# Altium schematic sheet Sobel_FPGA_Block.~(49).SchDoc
size A1
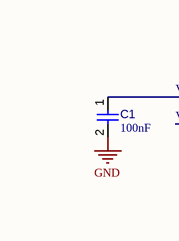
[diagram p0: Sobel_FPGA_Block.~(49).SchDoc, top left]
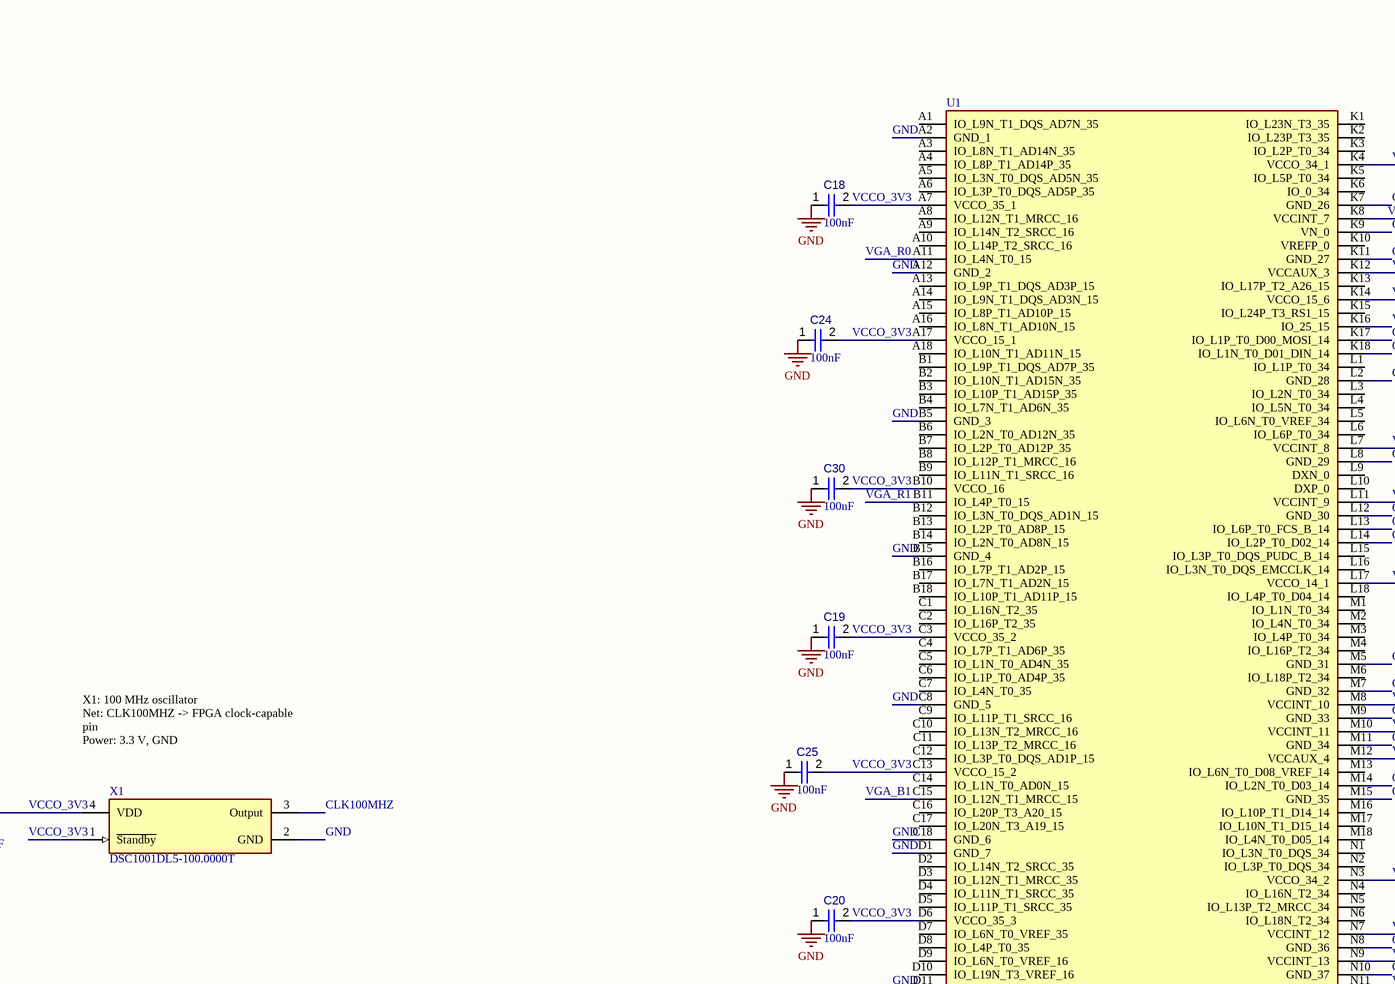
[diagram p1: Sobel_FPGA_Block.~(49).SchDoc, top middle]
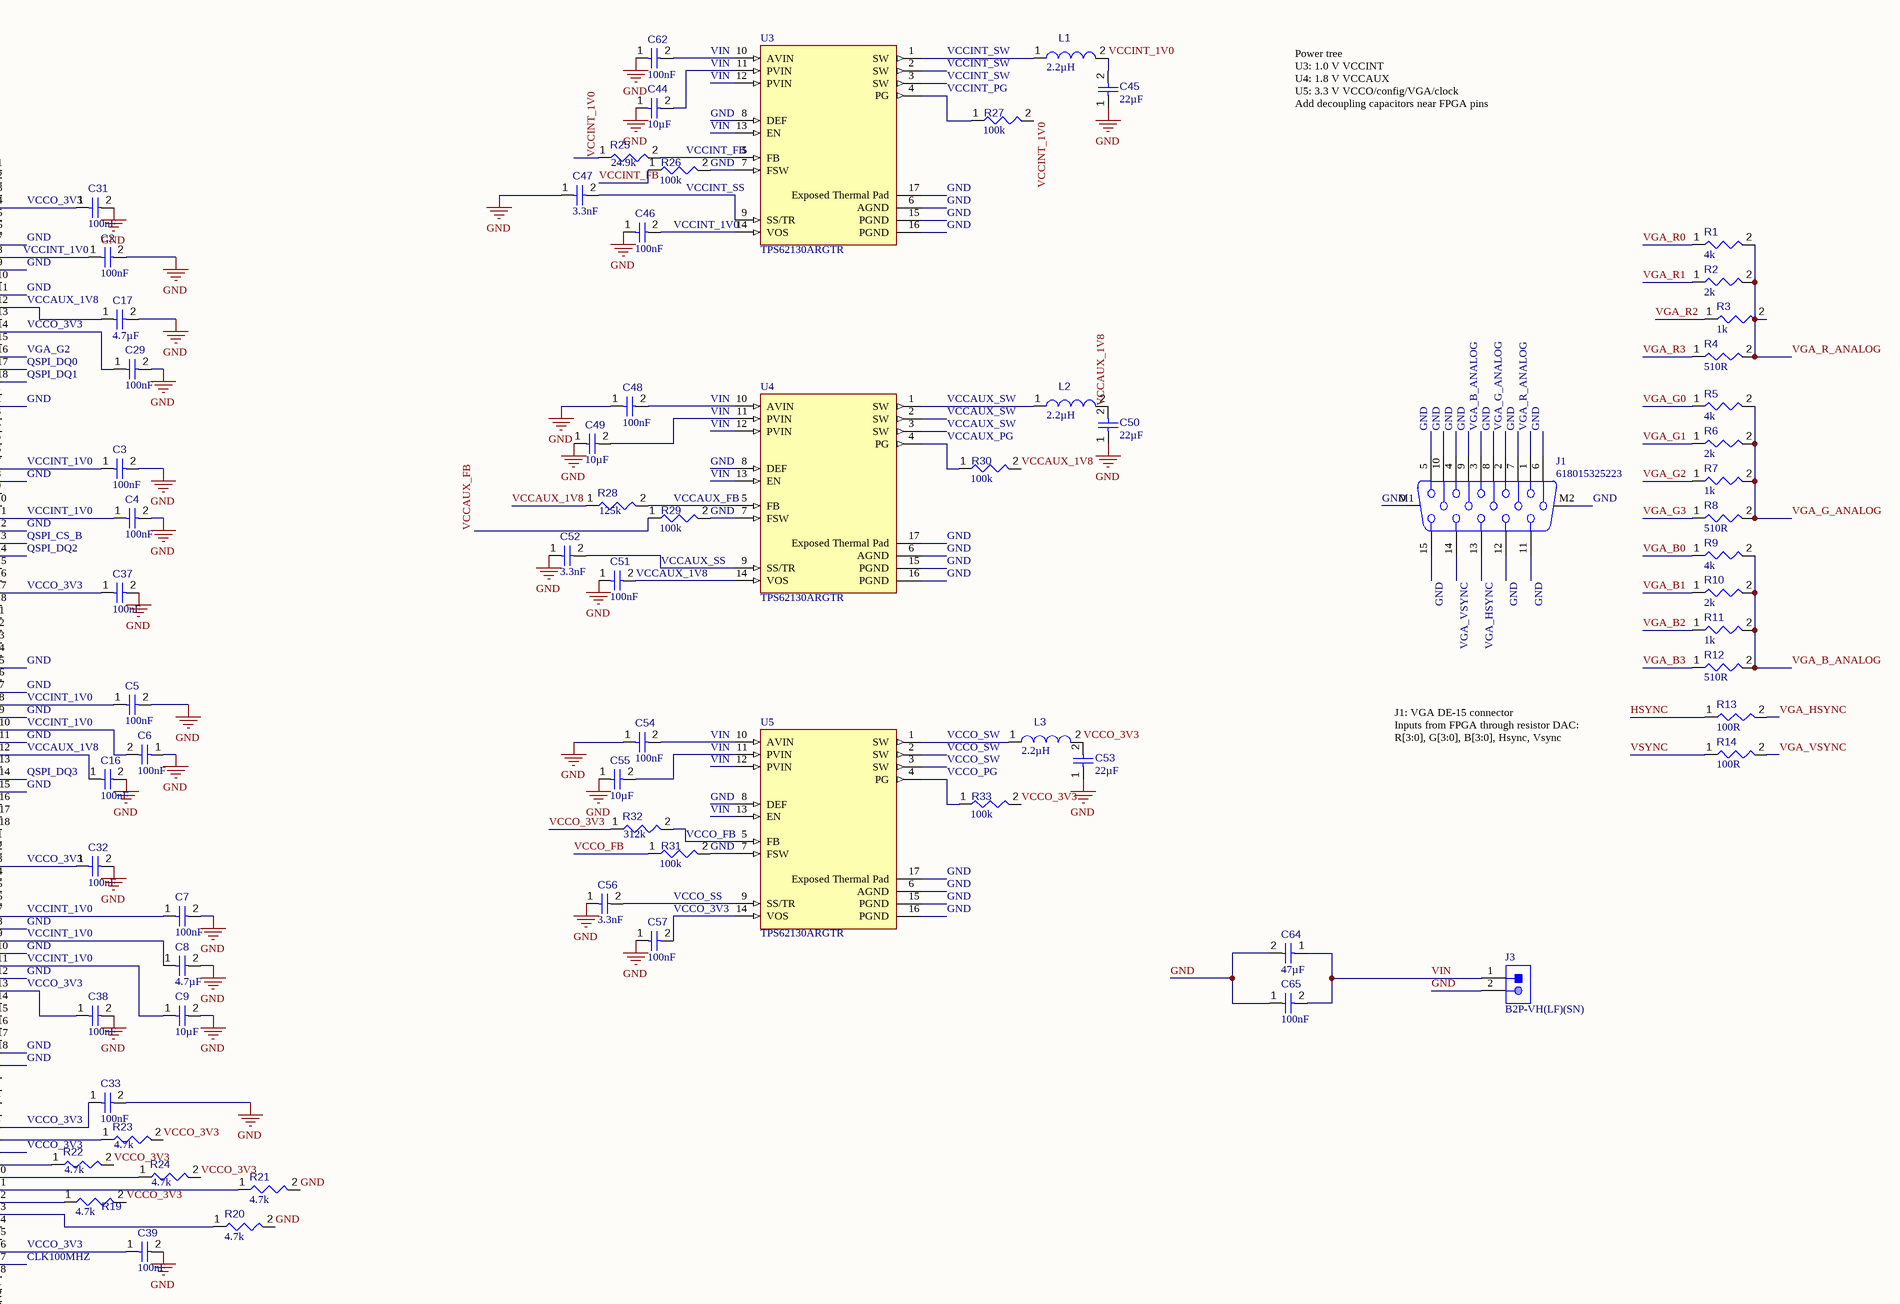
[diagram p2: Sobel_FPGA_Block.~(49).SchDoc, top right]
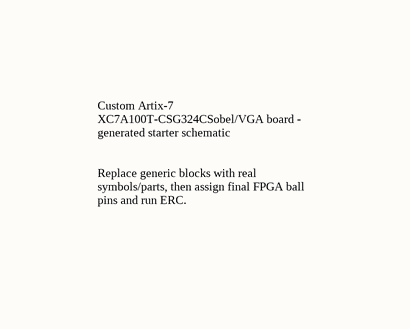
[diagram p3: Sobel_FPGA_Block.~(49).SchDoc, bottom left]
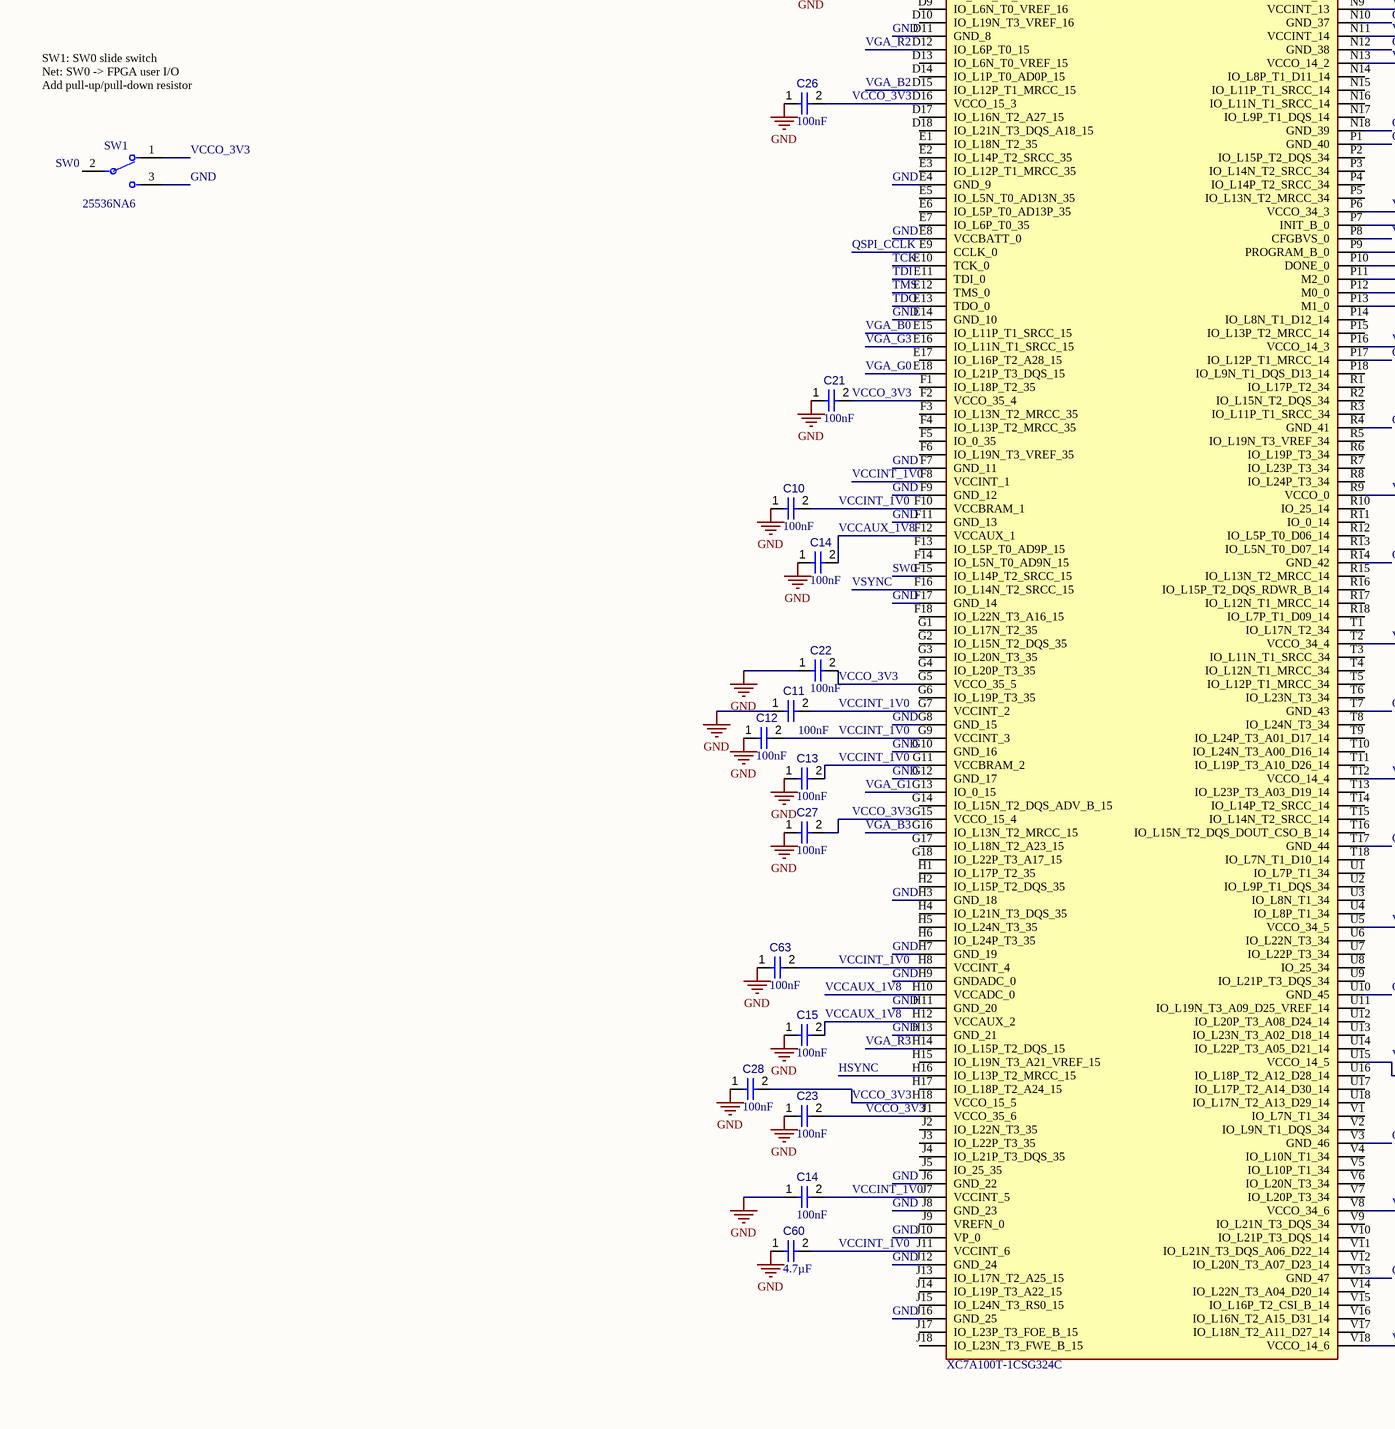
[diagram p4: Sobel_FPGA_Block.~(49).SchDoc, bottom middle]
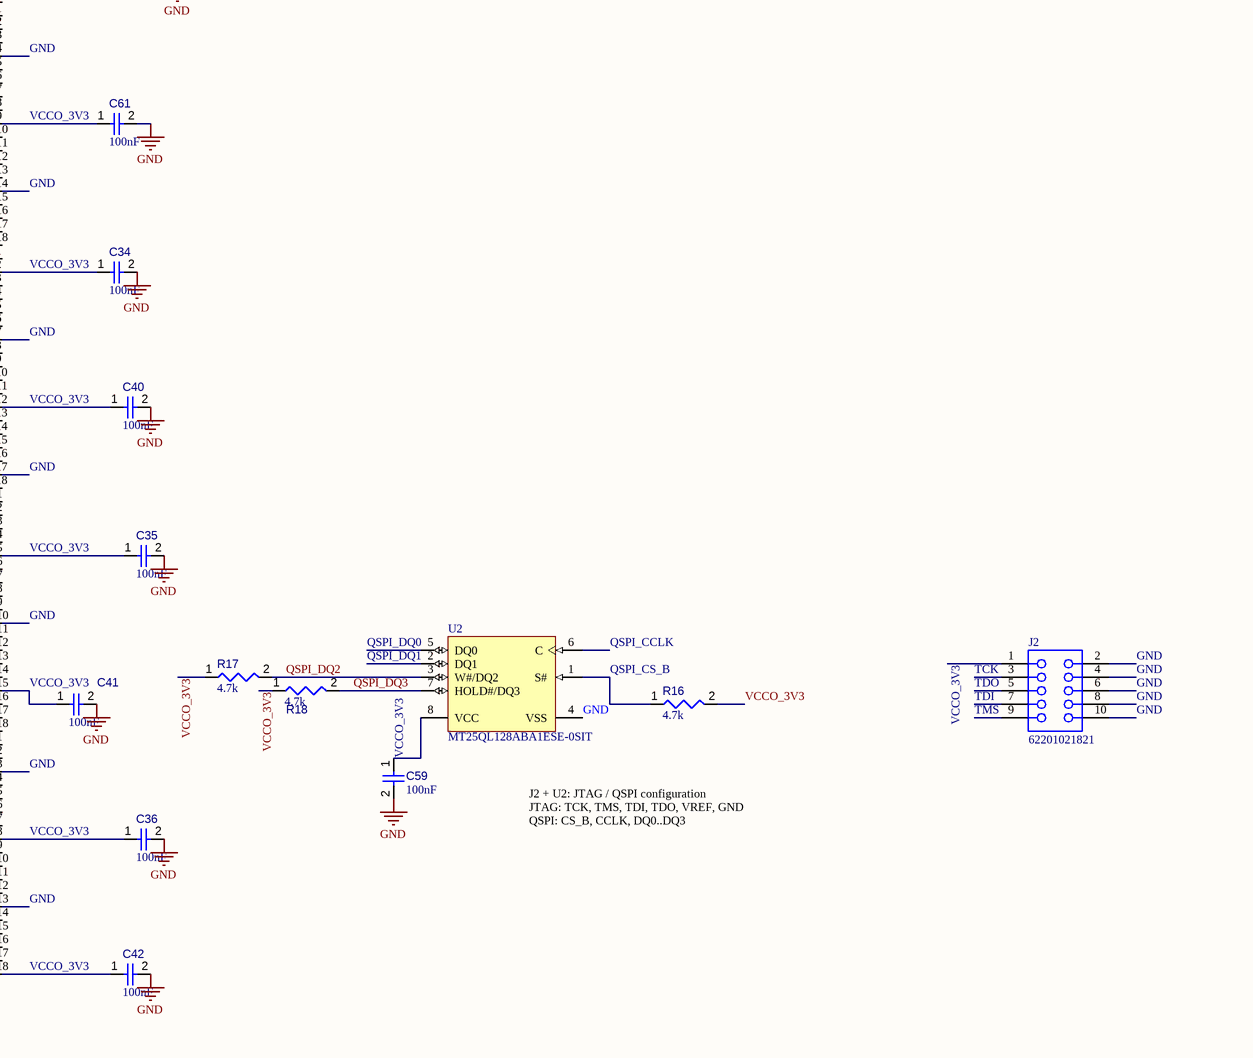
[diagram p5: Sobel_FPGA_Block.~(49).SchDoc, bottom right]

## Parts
(Parts that share a designator on the sheet are numbered #1, #2 ... from top to bottom, then left to right.)
C1  value 100nF  [CAPC1005X56X25NL10T15]  (hidden comment: Capacitor 6.8 nF +/- 10% 16 V 0402)
C2  value 100nF  [CAPC1005X56X25NL10T15]  (hidden comment: Capacitor 6.8 nF +/- 10% 16 V 0402)
C3  value 100nF  [CAPC1005X56X25NL10T15]  (hidden comment: Capacitor 6.8 nF +/- 10% 16 V 0402)
C4  value 100nF  [CAPC1005X56X25NL10T15]  (hidden comment: Capacitor 6.8 nF +/- 10% 16 V 0402)
C5  value 100nF  [CAPC1005X56X25NL10T15]  (hidden comment: Capacitor 6.8 nF +/- 10% 16 V 0402)
C6  value 100nF  [CAPC1005X56X25NL10T15]  (hidden comment: Capacitor 6.8 nF +/- 10% 16 V 0402)
C7  value 100nF  [CAPC1005X56X25NL10T15]  (hidden comment: Capacitor 6.8 nF +/- 10% 16 V 0402)
C8  value 4.7µF  [CAPC3216X180X50NL20T25]  (hidden comment: Capacitor 10 uF +/- 10% 16 V 1206)
C9  value 10µF  [CAPC3216X180X50NL20T25]  (hidden comment: Capacitor 10 uF +/- 10% 16 V 1206)
C10  value 100nF  [CAPC1005X56X25NL10T15]  (hidden comment: Capacitor 6.8 nF +/- 10% 16 V 0402)
C11  value 100nF  [CAPC1005X56X25NL10T15]  (hidden comment: Capacitor 6.8 nF +/- 10% 16 V 0402)
C12  value 100nF  [CAPC1005X56X25NL10T15]  (hidden comment: Capacitor 6.8 nF +/- 10% 16 V 0402)
C13  value 100nF  [CAPC1005X56X25NL10T15]  (hidden comment: Capacitor 6.8 nF +/- 10% 16 V 0402)
C14#1  value 100nF  [CAPC1005X56X25NL10T15]  (hidden comment: Capacitor 6.8 nF +/- 10% 16 V 0402)
C14#2  value 100nF  [CAPC1005X56X25NL10T15]  (hidden comment: Capacitor 6.8 nF +/- 10% 16 V 0402)
C15  value 100nF  [CAPC1005X56X25NL10T15]  (hidden comment: Capacitor 6.8 nF +/- 10% 16 V 0402)
C16  value 100nF  [CAPC1005X56X25NL10T15]  (hidden comment: Capacitor 6.8 nF +/- 10% 16 V 0402)
C17  value 4.7µF  [CAPC3216X180X50NL20T25]  (hidden comment: Capacitor 10 uF +/- 10% 16 V 1206)
C18  value 100nF  [CAPC1005X56X25NL10T15]  (hidden comment: Capacitor 6.8 nF +/- 10% 16 V 0402)
C19  value 100nF  [CAPC1005X56X25NL10T15]  (hidden comment: Capacitor 6.8 nF +/- 10% 16 V 0402)
C20  value 100nF  [CAPC1005X56X25NL10T15]  (hidden comment: Capacitor 6.8 nF +/- 10% 16 V 0402)
C21  value 100nF  [CAPC1005X56X25NL10T15]  (hidden comment: Capacitor 6.8 nF +/- 10% 16 V 0402)
C22  value 100nF  [CAPC1005X56X25NL10T15]  (hidden comment: Capacitor 6.8 nF +/- 10% 16 V 0402)
C23  value 100nF  [CAPC1005X56X25NL10T15]  (hidden comment: Capacitor 6.8 nF +/- 10% 16 V 0402)
C24  value 100nF  [CAPC1005X56X25NL10T15]  (hidden comment: Capacitor 6.8 nF +/- 10% 16 V 0402)
C25  value 100nF  [CAPC1005X56X25NL10T15]  (hidden comment: Capacitor 6.8 nF +/- 10% 16 V 0402)
C26  value 100nF  [CAPC1005X56X25NL10T15]  (hidden comment: Capacitor 6.8 nF +/- 10% 16 V 0402)
C27  value 100nF  [CAPC1005X56X25NL10T15]  (hidden comment: Capacitor 6.8 nF +/- 10% 16 V 0402)
C28  value 100nF  [CAPC1005X56X25NL10T15]  (hidden comment: Capacitor 6.8 nF +/- 10% 16 V 0402)
C29  value 100nF  [CAPC1005X56X25NL10T15]  (hidden comment: Capacitor 6.8 nF +/- 10% 16 V 0402)
C30  value 100nF  [CAPC1005X56X25NL10T15]  (hidden comment: Capacitor 6.8 nF +/- 10% 16 V 0402)
C31  value 100nF  [CAPC1005X56X25NL10T15]  (hidden comment: Capacitor 6.8 nF +/- 10% 16 V 0402)
C32  value 100nF  [CAPC1005X56X25NL10T15]  (hidden comment: Capacitor 6.8 nF +/- 10% 16 V 0402)
C33  value 100nF  [CAPC1005X56X25NL10T15]  (hidden comment: Capacitor 6.8 nF +/- 10% 16 V 0402)
C34  value 100nF  [CAPC1005X56X25NL10T15]  (hidden comment: Capacitor 6.8 nF +/- 10% 16 V 0402)
C35  value 100nF  [CAPC1005X56X25NL10T15]  (hidden comment: Capacitor 6.8 nF +/- 10% 16 V 0402)
C36  value 100nF  [CAPC1005X56X25NL10T15]  (hidden comment: Capacitor 6.8 nF +/- 10% 16 V 0402)
C37  value 100nF  [CAPC1005X56X25NL10T15]  (hidden comment: Capacitor 6.8 nF +/- 10% 16 V 0402)
C38  value 100nF  [CAPC1005X56X25NL10T15]  (hidden comment: Capacitor 6.8 nF +/- 10% 16 V 0402)
C39  value 100nF  [CAPC1005X56X25NL10T15]  (hidden comment: Capacitor 6.8 nF +/- 10% 16 V 0402)
C40  value 100nF  [CAPC1005X56X25NL10T15]  (hidden comment: Capacitor 6.8 nF +/- 10% 16 V 0402)
C41  value 100nF  [CAPC1005X56X25NL10T15]  (hidden comment: Capacitor 6.8 nF +/- 10% 16 V 0402)
C42  value 100nF  [CAPC1005X56X25NL10T15]  (hidden comment: Capacitor 6.8 nF +/- 10% 16 V 0402)
C44  value 10µF  [CAPC3216X180X50NL20T25]  (hidden comment: Capacitor 10 uF +/- 10% 16 V 1206)
C45  value 22µF  [CAPC3216X180X50NL20T25]  (hidden comment: Capacitor 10 uF +/- 10% 16 V 1206)
C46  value 100nF  [CAPC1005X56X25NL10T15]  (hidden comment: Capacitor 6.8 nF +/- 10% 16 V 0402)
C47  value 3.3nF  [CAPC1005X56X25NL10T15]  (hidden comment: Capacitor 6.8 nF +/- 10% 16 V 0402)
C48  value 100nF  [CAPC1005X56X25NL10T15]  (hidden comment: Capacitor 6.8 nF +/- 10% 16 V 0402)
C49  value 10µF  [CAPC3216X180X50NL20T25]  (hidden comment: Capacitor 10 uF +/- 10% 16 V 1206)
C50  value 22µF  [CAPC3216X180X50NL20T25]  (hidden comment: Capacitor 10 uF +/- 10% 16 V 1206)
C51  value 100nF  [CAPC1005X56X25NL10T15]  (hidden comment: Capacitor 6.8 nF +/- 10% 16 V 0402)
C52  value 3.3nF  [CAPC1005X56X25NL10T15]  (hidden comment: Capacitor 6.8 nF +/- 10% 16 V 0402)
C53  value 22µF  [CAPC3216X180X50NL20T25]  (hidden comment: Capacitor 10 uF +/- 10% 16 V 1206)
C54  value 100nF  [CAPC1005X56X25NL10T15]  (hidden comment: Capacitor 6.8 nF +/- 10% 16 V 0402)
C55  value 10µF  [CAPC3216X180X50NL20T25]  (hidden comment: Capacitor 10 uF +/- 10% 16 V 1206)
C56  value 3.3nF  [CAPC1005X56X25NL10T15]  (hidden comment: Capacitor 6.8 nF +/- 10% 16 V 0402)
C57  value 100nF  [CAPC1005X56X25NL10T15]  (hidden comment: Capacitor 6.8 nF +/- 10% 16 V 0402)
C59  value 100nF  [CAPC1005X56X25NL10T15]  (hidden comment: Capacitor 6.8 nF +/- 10% 16 V 0402)
C60  value 4.7µF  [CAPC3216X180X50NL20T25]  (hidden comment: Capacitor 10 uF +/- 10% 16 V 1206)
C61  value 100nF  [CAPC1005X56X25NL10T15]  (hidden comment: Capacitor 6.8 nF +/- 10% 16 V 0402)
C62  value 100nF  [CAPC1005X56X25NL10T15]  (hidden comment: Capacitor 6.8 nF +/- 10% 16 V 0402)
C63  value 100nF  [CAPC1005X56X25NL10T15]  (hidden comment: Capacitor 6.8 nF +/- 10% 16 V 0402)
C64  value 47µF  [CAPC3216X180X50NL20T25]  (hidden comment: Capacitor 10 uF +/- 10% 16 V 1206)
C65  value 100nF  [CAPC1005X56X25NL10T15]  (hidden comment: Capacitor 6.8 nF +/- 10% 16 V 0402)
J1  618015325223  [618015325223]
J2  62201021821  [62201021821]
J3  B2P-VH(LF)(SN)  [JST-B2P-VH(LF)(SN)_V]
L1  value 2.2µH  [SUSUMU-PCMB063T_V]  (hidden comment: PCMB063T-2R2MS)
L2  value 2.2µH  [SUSUMU-PCMB063T_V]  (hidden comment: PCMB063T-2R2MS)
L3  value 2.2µH  [SUSUMU-PCMB063T_V]  (hidden comment: PCMB063T-2R2MS)
R1  value 4k  [RESA60-630X240]  (hidden comment: MFR-25FBF52-475R)
R2  value 2k  [RESA60-630X240]  (hidden comment: MFR-25FBF52-475R)
R3  value 1k  [RESA60-630X240]  (hidden comment: MFR-25FBF52-475R)
R4  value 510R  [RESA60-630X240]  (hidden comment: MFR-25FBF52-475R)
R5  value 4k  [RESA60-630X240]  (hidden comment: MFR-25FBF52-475R)
R6  value 2k  [RESA60-630X240]  (hidden comment: MFR-25FBF52-475R)
R7  value 1k  [RESA60-630X240]  (hidden comment: MFR-25FBF52-475R)
R8  value 510R  [RESA60-630X240]  (hidden comment: MFR-25FBF52-475R)
R9  value 4k  [RESA60-630X240]  (hidden comment: MFR-25FBF52-475R)
R10  value 2k  [RESA60-630X240]  (hidden comment: MFR-25FBF52-475R)
R11  value 1k  [RESA60-630X240]  (hidden comment: MFR-25FBF52-475R)
R12  value 510R  [RESA60-630X240]  (hidden comment: MFR-25FBF52-475R)
R13  value 100R  [RESA60-630X240]  (hidden comment: MFR-25FBF52-475R)
R14  value 100R  [RESA60-630X240]  (hidden comment: MFR-25FBF52-475R)
R16  value 4.7k  [RESC0402(1005)_L]  (hidden comment: 84D5KR2F)
R17  value 4.7k  [RESC0402(1005)_L]  (hidden comment: 84D5KR2F)
R18  value 4.7k  [RESC0402(1005)_L]  (hidden comment: 84D5KR2F)
R19  value 4.7k  [RESC0402(1005)_L]  (hidden comment: 84D5KR2F)
R20  value 4.7k  [RESC0402(1005)_L]  (hidden comment: 84D5KR2F)
R21  value 4.7k  [RESC0402(1005)_L]  (hidden comment: 84D5KR2F)
R22  value 4.7k  [RESC0402(1005)_L]  (hidden comment: 84D5KR2F)
R23  value 4.7k  [RESC0402(1005)_L]  (hidden comment: 84D5KR2F)
R24  value 4.7k  [RESC0402(1005)_L]  (hidden comment: 84D5KR2F)
R25  value 24.9k  [RESC0402(1005)_L]  (hidden comment: 84D5KR2F)
R26  value 100k  [RESC0402(1005)_L]  (hidden comment: 84D5KR2F)
R27  value 100k  [RESC0402(1005)_L]  (hidden comment: 84D5KR2F)
R28  value 125k  [RESC0402(1005)_L]  (hidden comment: 84D5KR2F)
R29  value 100k  [RESC0402(1005)_L]  (hidden comment: 84D5KR2F)
R30  value 100k  [RESC0402(1005)_L]  (hidden comment: 84D5KR2F)
R31  value 100k  [RESC0402(1005)_L]  (hidden comment: 84D5KR2F)
R32  value 312k  [RESC0402(1005)_L]  (hidden comment: 84D5KR2F)
R33  value 100k  [RESC0402(1005)_L]  (hidden comment: 84D5KR2F)
SW1  25536NA6  [FP-25536NA6-0]
U1  XC7A100T-1CSG324C  [BGA324C80P18X18_1500X1500X150]
U2  MT25QL128ABA1ESE-0SIT  [MICT-SE-8_M]
U3  TPS62130ARGTR  [FP-RGT0016C-IPC_C]
U4  TPS62130ARGTR  [FP-RGT0016C-IPC_C]
U5  TPS62130ARGTR  [FP-RGT0016C-IPC_C]
X1  DSC1001DL5-100.0000T  [FP-CDFN2520-4LD-PL-1-MFG]

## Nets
GND: C1.2 C2.2 C3.2 C4.2 C5.2 C6.1 C7.2 C8.2 C9.2 C10.1 C11.1 C12.1 C13.1 C14#1.1 C14#2.1 C15.1 C16.2 C17.2 C18.1 C19.1 C20.1 C21.1 C22.1 C23.1 C24.1 C25.1 C26.1 C27.1 C28.1 C29.2 C30.1 C31.2 C32.2 C33.2 C34.2 C35.2 C36.2 C37.2 C38.2 C39.2 C40.2 C41.2 C42.2 C44.1 C45.1 C46.1 C47.1 C48.1 C49.1 C50.1 C51.1 C52.1 C53.1 C54.1 C55.1 C56.1 C57.1 C59.2 C60.1 C61.2 C62.1 C63.1 C64.2 C65.1 J1.4 J1.5 J1.6 J1.7 J1.8 J1.9 J1.10 J1.11 J1.12 J1.15 J1.M1 J1.M2 J2.2 J2.4 J2.6 J2.8 J2.10 J3.2 R20.2 R21.2 R26.2 R29.2 R31.2 SW1.3 U1.A2(GND_1) U1.A12(GND_2) U1.B5(GND_3) U1.B15(GND_4) U1.C8(GND_5) U1.C18(GND_6) U1.D1(GND_7) U1.D11(GND_8) U1.E4(GND_9) U1.E8(VCCBATT_0) U1.E14(GND_10) U1.F7(GND_11) U1.F9(GND_12) U1.F11(GND_13) U1.F17(GND_14) U1.G8(GND_15) U1.G10(GND_16) U1.G12(GND_17) U1.H3(GND_18) U1.H7(GND_19) U1.H9(GNDADC_0) U1.H11(GND_20) U1.H13(GND_21) U1.J6(GND_22) U1.J8(GND_23) U1.J10(VP_0) U1.J12(GND_24) U1.J16(GND_25) U1.K7(GND_26) U1.K9(VN_0) U1.K11(GND_27) U1.L2(GND_28) U1.L8(GND_29) U1.L12(GND_30) U1.M5(GND_31) U1.M7(GND_32) U1.M9(GND_33) U1.M11(GND_34) U1.M15(GND_35) U1.N8(GND_36) U1.N10(GND_37) U1.N12(GND_38) U1.N18(GND_39) U1.P1(GND_40) U1.R4(GND_41) U1.R14(GND_42) U1.T7(GND_43) U1.T17(GND_44) U1.U10(GND_45) U1.V3(GND_46) U1.V13(GND_47) U2.4(VSS) U3.6(AGND) U3.7(FSW) U3.8(DEF) U3.15(PGND) U3.16(PGND) U3.17(Exposed_Thermal_Pad) U4.6(AGND) U4.7(FSW) U4.8(DEF) U4.15(PGND) U4.16(PGND) U4.17(Exposed_Thermal_Pad) U5.6(AGND) U5.7(FSW) U5.8(DEF) U5.15(PGND) U5.16(PGND) U5.17(Exposed_Thermal_Pad) X1.2(GND)
 VCCO_3V3: C1.1 C18.2 C19.2 C20.2 C21.2 C22.2 C23.2 C24.2 C25.2 C26.2 C27.2 C28.2 C29.1 C30.2 C31.1 C32.1 C33.1 C34.1 C35.1 C36.1 C37.1 C38.1 C39.1 C40.1 C41.1 C42.1 C53.2 C57.2 C59.1 C61.1 J2.1 L3.2 R16.2 R17.1 R18.1 R19.2 R22.2 R23.2 R24.2 R32.1 R33.2 SW1.1 U1.A7(VCCO_35_1) U1.A17(VCCO_15_1) U1.B10(VCCO_16) U1.C3(VCCO_35_2) U1.C13(VCCO_15_2) U1.D6(VCCO_35_3) U1.D16(VCCO_15_3) U1.F2(VCCO_35_4) U1.G5(VCCO_35_5) U1.G15(VCCO_15_4) U1.H18(VCCO_15_5) U1.J1(VCCO_35_6) U1.K4(VCCO_34_1) U1.K14(VCCO_15_6) U1.L17(VCCO_14_1) U1.N3(VCCO_34_2) U1.N13(VCCO_14_2) U1.P6(VCCO_34_3) U1.P8(CFGBVS_0) U1.P16(VCCO_14_3) U1.R9(VCCO_0) U1.T2(VCCO_34_4) U1.T12(VCCO_14_4) U1.U5(VCCO_34_5) U1.U15(VCCO_14_5) U1.V8(VCCO_34_6) U1.V18(VCCO_14_6) U2.8(VCC) U5.14(VOS) X1.1(~{Standby}) X1.4(VDD)  [also labelled VCCO_3V3]
CLK100MHZ: U1.P17(IO_L12P_T1_MRCC_14) X1.3(Output)
HSYNC: R13.1 U1.H16(IO_L13P_T2_MRCC_15)
QSPI_CCLK: U1.E9(CCLK_0) U2.6(C)
QSPI_CS_B: R16.1 U1.L13(IO_L6P_T0_FCS_B_14) U2.1(S#)
QSPI_DQ0: U1.K17(IO_L1P_T0_D00_MOSI_14) U2.5(DQ0)
QSPI_DQ1: U1.K18(IO_L1N_T0_D01_DIN_14) U2.2(DQ1)
QSPI_DQ2: R17.2 U1.L14(IO_L2P_T0_D02_14) U2.3(W#/DQ2)
QSPI_DQ3: R18.2 U1.M14(IO_L2N_T0_D03_14) U2.7(HOLD#/DQ3)
SW0: U1.F15(IO_L14P_T2_SRCC_15)
TCK: J2.3 U1.E10(TCK_0)
TDI: J2.7 U1.E11(TDI_0)
TDO: J2.5 U1.E13(TDO_0)
TMS: J2.9 U1.E12(TMS_0)
VCCAUX_1V8: C14#1.2 C15.2 C16.1 C17.1 C50.2 C51.2 L2.2 R28.1 R30.2 U1.F12(VCCAUX_1) U1.H10(VCCADC_0) U1.H12(VCCAUX_2) U1.K12(VCCAUX_3) U1.M12(VCCAUX_4) U4.14(VOS)
VCCAUX_FB: R28.2 R29.1 U4.5(FB)  [also labelled VCCAUX_FB ]
VCCAUX_PG: R30.1 U4.4(PG)
VCCAUX_SS: C52.2 U4.9(SS/TR)
VCCAUX_SW: L2.1 U4.1(SW) U4.2(SW) U4.3(SW)
VCCINT_1V0: C2.1 C3.1 C4.1 C5.1 C6.2 C7.1 C8.1 C9.1 C10.2 C11.2 C12.2 C13.2 C14#2.2 C45.2 C46.2 C60.2 C63.2 L1.2 R25.1 R27.2 U1.F8(VCCINT_1) U1.F10(VCCBRAM_1) U1.G7(VCCINT_2) U1.G9(VCCINT_3) U1.G11(VCCBRAM_2) U1.H8(VCCINT_4) U1.J7(VCCINT_5) U1.J11(VCCINT_6) U1.K8(VCCINT_7) U1.L7(VCCINT_8) U1.L11(VCCINT_9) U1.M8(VCCINT_10) U1.M10(VCCINT_11) U1.N7(VCCINT_12) U1.N9(VCCINT_13) U1.N11(VCCINT_14) U3.14(VOS)
VCCINT_FB: R25.2 R26.1 U3.5(FB)
VCCINT_PG: R27.1 U3.4(PG)
VCCINT_SS: C47.2 U3.9(SS/TR)
VCCINT_SW: L1.1 U3.1(SW) U3.2(SW) U3.3(SW)
VCCO_FB: R31.1 R32.2 U5.5(FB)
VCCO_PG: R33.1 U5.4(PG)
VCCO_SS: C56.2 U5.9(SS/TR)
VCCO_SW: L3.1 U5.1(SW) U5.2(SW) U5.3(SW)
VGA_B0: R9.1 U1.E15(IO_L11P_T1_SRCC_15)
VGA_B1: R10.1 U1.C15(IO_L12N_T1_MRCC_15)
VGA_B2: R11.1 U1.D15(IO_L12P_T1_MRCC_15)
VGA_B3: R12.1 U1.G16(IO_L13N_T2_MRCC_15)
VGA_B_ANALOG: J1.3 R9.2 R10.2 R11.2 R12.2
VGA_G0: R5.1 U1.E18(IO_L21P_T3_DQS_15)
VGA_G1: R6.1 U1.G13(IO_0_15)
VGA_G2: R7.1 U1.K16(IO_25_15)
VGA_G3: R8.1 U1.E16(IO_L11N_T1_SRCC_15)
VGA_G_ANALOG: J1.2 R5.2 R6.2 R7.2 R8.2
VGA_HSYNC: J1.13 R13.2
VGA_R0: R1.1 U1.A11(IO_L4N_T0_15)
VGA_R1: R2.1 U1.B11(IO_L4P_T0_15)
VGA_R2: R3.1 U1.D12(IO_L6P_T0_15)
VGA_R3: R4.1 U1.H14(IO_L15P_T2_DQS_15)
VGA_R_ANALOG: J1.1 R1.2 R2.2 R3.2 R4.2
VGA_VSYNC: J1.14 R14.2
VIN: C44.2 C48.2 C49.2 C54.2 C55.2 C62.2 C64.1 C65.2 J3.1 U3.10(AVIN) U3.11(PVIN) U3.12(PVIN) U3.13(EN) U4.10(AVIN) U4.11(PVIN) U4.12(PVIN) U4.13(EN) U5.10(AVIN) U5.11(PVIN) U5.12(PVIN) U5.13(EN)
VSYNC: R14.1 U1.F16(IO_L14N_T2_SRCC_15)
NetR19_1: R19.1 U1.P12(M0_0)
NetR20_1: R20.1 U1.P13(M1_0)
NetR21_1: R21.1 U1.P11(M2_0)
NetR22_1: R22.1 U1.P9(PROGRAM_B_0)
NetR23_1: R23.1 U1.P7(INIT_B_0)
NetR24_1: R24.1 U1.P10(DONE_0)

Not connected (* = marked no-connect by the designer): SW1 2; U1 A1(IO_L9N_T1_DQS_AD7N_35) A3(IO_L8N_T1_AD14N_35) A4(IO_L8P_T1_AD14P_35) A5(IO_L3N_T0_DQS_AD5N_35) A6(IO_L3P_T0_DQS_AD5P_35) A8(IO_L12N_T1_MRCC_16) A9(IO_L14N_T2_SRCC_16) A10(IO_L14P_T2_SRCC_16) A13(IO_L9P_T1_DQS_AD3P_15) A14(IO_L9N_T1_DQS_AD3N_15) A15(IO_L8P_T1_AD10P_15) A16(IO_L8N_T1_AD10N_15) A18(IO_L10N_T1_AD11N_15) B1(IO_L9P_T1_DQS_AD7P_35) B2(IO_L10N_T1_AD15N_35) B3(IO_L10P_T1_AD15P_35) B4(IO_L7N_T1_AD6N_35) B6(IO_L2N_T0_AD12N_35) B7(IO_L2P_T0_AD12P_35) B8(IO_L12P_T1_MRCC_16) B9(IO_L11N_T1_SRCC_16) B12(IO_L3N_T0_DQS_AD1N_15) B13(IO_L2P_T0_AD8P_15) B14(IO_L2N_T0_AD8N_15) B16(IO_L7P_T1_AD2P_15) B17(IO_L7N_T1_AD2N_15) B18(IO_L10P_T1_AD11P_15) C1(IO_L16N_T2_35) C2(IO_L16P_T2_35) C4(IO_L7P_T1_AD6P_35) C5(IO_L1N_T0_AD4N_35) C6(IO_L1P_T0_AD4P_35) C7(IO_L4N_T0_35) C9(IO_L11P_T1_SRCC_16) C10(IO_L13N_T2_MRCC_16) C11(IO_L13P_T2_MRCC_16) C12(IO_L3P_T0_DQS_AD1P_15) C14(IO_L1N_T0_AD0N_15) C16(IO_L20P_T3_A20_15) C17(IO_L20N_T3_A19_15) D2(IO_L14N_T2_SRCC_35) D3(IO_L12N_T1_MRCC_35) D4(IO_L11N_T1_SRCC_35) D5(IO_L11P_T1_SRCC_35) D7(IO_L6N_T0_VREF_35) D8(IO_L4P_T0_35) D9(IO_L6N_T0_VREF_16) D10(IO_L19N_T3_VREF_16) D13(IO_L6N_T0_VREF_15) D14(IO_L1P_T0_AD0P_15) D17(IO_L16N_T2_A27_15) D18(IO_L21N_T3_DQS_A18_15) E1(IO_L18N_T2_35) E2(IO_L14P_T2_SRCC_35) E3(IO_L12P_T1_MRCC_35) E5(IO_L5N_T0_AD13N_35) E6(IO_L5P_T0_AD13P_35) E7(IO_L6P_T0_35) E17(IO_L16P_T2_A28_15) F1(IO_L18P_T2_35) F3(IO_L13N_T2_MRCC_35) F4(IO_L13P_T2_MRCC_35) F5(IO_0_35) F6(IO_L19N_T3_VREF_35) F13(IO_L5P_T0_AD9P_15) F14(IO_L5N_T0_AD9N_15) F18(IO_L22N_T3_A16_15) G1(IO_L17N_T2_35) G2(IO_L15N_T2_DQS_35) G3(IO_L20N_T3_35) G4(IO_L20P_T3_35) G6(IO_L19P_T3_35) G14(IO_L15N_T2_DQS_ADV_B_15) G17(IO_L18N_T2_A23_15) G18(IO_L22P_T3_A17_15) H1(IO_L17P_T2_35) H2(IO_L15P_T2_DQS_35) H4(IO_L21N_T3_DQS_35) H5(IO_L24N_T3_35) H6(IO_L24P_T3_35) H15(IO_L19N_T3_A21_VREF_15) H17(IO_L18P_T2_A24_15) J2(IO_L22N_T3_35) J3(IO_L22P_T3_35) J4(IO_L21P_T3_DQS_35) J5(IO_25_35) J9(VREFN_0) J13(IO_L17N_T2_A25_15) J14(IO_L19P_T3_A22_15) J15(IO_L24N_T3_RS0_15) J17(IO_L23P_T3_FOE_B_15) J18(IO_L23N_T3_FWE_B_15) K1(IO_L23N_T3_35) K2(IO_L23P_T3_35) K3(IO_L2P_T0_34) K5(IO_L5P_T0_34) K6(IO_0_34) K10(VREFP_0) K13(IO_L17P_T2_A26_15) K15(IO_L24P_T3_RS1_15) L1(IO_L1P_T0_34) L3(IO_L2N_T0_34) L4(IO_L5N_T0_34) L5(IO_L6N_T0_VREF_34) L6(IO_L6P_T0_34) L9(DXN_0) L10(DXP_0) L15(IO_L3P_T0_DQS_PUDC_B_14) L16(IO_L3N_T0_DQS_EMCCLK_14) L18(IO_L4P_T0_D04_14) M1(IO_L1N_T0_34) M2(IO_L4N_T0_34) M3(IO_L4P_T0_34) M4(IO_L16P_T2_34) M6(IO_L18P_T2_34) M13(IO_L6N_T0_D08_VREF_14) M16(IO_L10P_T1_D14_14) M17(IO_L10N_T1_D15_14) M18(IO_L4N_T0_D05_14) N1(IO_L3N_T0_DQS_34) N2(IO_L3P_T0_DQS_34) N4(IO_L16N_T2_34) N5(IO_L13P_T2_MRCC_34) N6(IO_L18N_T2_34) N14(IO_L8P_T1_D11_14) N15(IO_L11P_T1_SRCC_14) N16(IO_L11N_T1_SRCC_14) N17(IO_L9P_T1_DQS_14) P2(IO_L15P_T2_DQS_34) P3(IO_L14N_T2_SRCC_34) P4(IO_L14P_T2_SRCC_34) P5(IO_L13N_T2_MRCC_34) P14(IO_L8N_T1_D12_14) P15(IO_L13P_T2_MRCC_14) P18(IO_L9N_T1_DQS_D13_14) R1(IO_L17P_T2_34) R2(IO_L15N_T2_DQS_34) R3(IO_L11P_T1_SRCC_34) R5(IO_L19N_T3_VREF_34) R6(IO_L19P_T3_34) R7(IO_L23P_T3_34) R8(IO_L24P_T3_34) R10(IO_25_14) R11(IO_0_14) R12(IO_L5P_T0_D06_14) R13(IO_L5N_T0_D07_14) R15(IO_L13N_T2_MRCC_14) R16(IO_L15P_T2_DQS_RDWR_B_14) R17(IO_L12N_T1_MRCC_14) R18(IO_L7P_T1_D09_14) T1(IO_L17N_T2_34) T3(IO_L11N_T1_SRCC_34) T4(IO_L12N_T1_MRCC_34) T5(IO_L12P_T1_MRCC_34) T6(IO_L23N_T3_34) T8(IO_L24N_T3_34) T9(IO_L24P_T3_A01_D17_14) T10(IO_L24N_T3_A00_D16_14) T11(IO_L19P_T3_A10_D26_14) T13(IO_L23P_T3_A03_D19_14) T14(IO_L14P_T2_SRCC_14) T15(IO_L14N_T2_SRCC_14) T16(IO_L15N_T2_DQS_DOUT_CSO_B_14) T18(IO_L7N_T1_D10_14) U1(IO_L7P_T1_34) U2(IO_L9P_T1_DQS_34) U3(IO_L8N_T1_34) U4(IO_L8P_T1_34) U6(IO_L22N_T3_34) U7(IO_L22P_T3_34) U8(IO_25_34) U9(IO_L21P_T3_DQS_34) U11(IO_L19N_T3_A09_D25_VREF_14) U12(IO_L20P_T3_A08_D24_14) U13(IO_L23N_T3_A02_D18_14) U14(IO_L22P_T3_A05_D21_14) U16(IO_L18P_T2_A12_D28_14) U17(IO_L17P_T2_A14_D30_14) U18(IO_L17N_T2_A13_D29_14) V1(IO_L7N_T1_34) V2(IO_L9N_T1_DQS_34) V4(IO_L10N_T1_34) V5(IO_L10P_T1_34) V6(IO_L20N_T3_34) V7(IO_L20P_T3_34) V9(IO_L21N_T3_DQS_34) V10(IO_L21P_T3_DQS_14) V11(IO_L21N_T3_DQS_A06_D22_14) V12(IO_L20N_T3_A07_D23_14) V14(IO_L22N_T3_A04_D20_14) V15(IO_L16P_T2_CSI_B_14) V16(IO_L16N_T2_A15_D31_14) V17(IO_L18N_T2_A11_D27_14)

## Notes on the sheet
- Power tree
  U3: 1.0 V VCCINT
  U4: 1.8 V VCCAUX
  U5: 3.3 V VCCO/config/VGA/clock
  Add decoupling capacitors near FPGA pins
- X1: 100 MHz oscillator
  Net: CLK100MHZ -> FPGA clock-capable pin
  Power: 3.3 V, GND
- J1: VGA DE-15 connector
  Inputs from FPGA through resistor DAC:
  R[3:0], G[3:0], B[3:0], Hsync, Vsync
- (near SW1) SW1: SW0 slide switch
  Net: SW0 -> FPGA user I/O
  Add pull-up/pull-down resistor
- Custom Artix-7 XC7A100T-CSG324CSobel/VGA board - generated starter schematic
- Replace generic blocks with real symbols/parts, then assign final FPGA ball pins and run ERC.
- J2 + U2: JTAG / QSPI configuration
  JTAG: TCK, TMS, TDI, TDO, VREF, GND
  QSPI: CS_B, CCLK, DQ0..DQ3
- Labels drawn without touching a wire or pin: SW0

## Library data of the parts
C1-C7 C10-C13 C14#1 C14#2 C15 C16 C18-C42 C46-C48 C51 C52 C54 C56 C57 C59 C61-C63 C65 = CMP-001-00000-6: Chip Capacitor, 6.8 nF, +/- 10%, 16 V, 0402 (1005 Metric); Capacitor Type: Ceramic; Voltage Rating: 16V
C8 C9 C17 C44 C45 C49 C50 C53 C55 C60 C64 = CMP-001-00016-6: Chip Capacitor, 10 uF, +/- 10%, 16 V, 1206 (3216 Metric); Capacitor Type: Ceramic; Voltage Rating: 16V
J1 = CMP-002-00072-1: D-sub, Female High Density Angled Pcb Connector Without Hex Screw, 15 Pins
J2 = CMP-002-00073-1: Connector Header Surface Mount 10 position 0.050" (1.27mm)-JTAG Connector; Gender: Female
J3 = CMP-002-00025-2: Male Header, Pitch 3.96 mm, 1 x 2 Position, Height 10.9 mm, Tail Length 3.7 mm, -25 to 85 degC, RoHS, Bulk; Manufacturer: JST
L1-L3 = CMP-006-00019-3: Shielded Wirewound Inductor, 2.2 uH, +/- 20%, -20 to 120 degC, 2-Pin SMD, RoHS, Tape and Reel
R1-R14 = CMP-009-00056-4: Axial Resistor, 475 Ohm, +/- 1%, 0.25 W, -55 to 155 degC, 2-Pin THD, RoHS, Bulk; Manufacturer: Yageo; Voltage Rating: 250V; Power: 250mW
R16-R33 = CMP-009-00111-2: 84K5 0.063W 1% 0402 (1005 Metric)  SMD; Power: 63mW
SW1 = CMP-011-00013-1: Switch Slide ON ON SPDT Side Slide 1A 30VDC 20000Cycles PC Pins Thru-Hole; Max Current Rating: 3A
U1 = XC7A100T-1CSG324C: IC FPGA ARTIX7 210 I/O 324CSBGA; Manufacturer_Name: AMD; Geometry.Height: 1.5mm
U2 = CMP-019-00049-1: 3.6 V 35 mA 128 Mbit 133 MHz Surface Mount FLASH - NOR Memory IC - SOIC-16; Min Supply Voltage: 2.7V; Memory Size: 16MB; Clock Frequency: 133MHz; Max Supply Voltage: 3.6V
U3-U5 = CMP-019-00050-1: 3-V to 17-V, 3-A step-down converter with DCS-control in 3x3 QFN package 16-VQFN -40 to 125; Output Current: 3A; Output Voltage: 6V; Nominal Supply Current: 17µA; Min Supply Voltage: 3V; Max Supply Voltage: 17V
X1 = CMP-00023-00003-1: 3.3 V 100 MHz Surface Mount Low-Power Precision CMOS Oscillator - VDFN-4; Frequency: 100MHz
